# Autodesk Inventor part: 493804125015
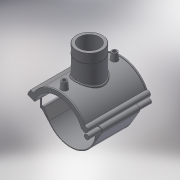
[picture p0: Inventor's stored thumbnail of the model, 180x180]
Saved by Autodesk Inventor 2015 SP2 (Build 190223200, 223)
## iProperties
Created: 2017-07
Part Number: 493804125015
Material: Generic
Description: PLASSON TRANSITION SADDLE 125-1.1/2"
Document SubType Name: Modeling
Designer: KIM
Density: 1 g/cm^3
Appearance: Default
Author: KIM
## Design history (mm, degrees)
derived "493804.ipt"
feature "Solid1::493804.ipt"
tag "TaggingFeature1"
body "Solid1"
other parameters: "d_" = 125, "B_" = 158, "H_" = 53, "L_" = 118, "d_t" = 6, "G_" = 44.845, "d148" = 1.875, "d160" = 1.875, "d169" = 2.1, "d192" = 4.2, "d0" = 125, "d1" = 145, "d2" = 158, "d3" = 31.25, "d4" = 118, "d5" = 0, "d6" = 0.1, "d8" = 0, "d19" = 6, "d20" = 6, "d21" = 70.8, "d23" = 0, "d24" = 35.4, "d26" = 0, "d27" = 3, "d28" = 3, "d29" = 3, "d30" = 41.66667, "d31" = 6, "d32" = 0, "d33" = 0, "d34" = 0.6, "d40" = 75.4, "d41" = 62.783, "d43" = 0, "d45" = 0, "d47" = 125.5, "d48" = 58.2985, "d50" = 0, "d70" = 15, "d72" = 0, "d73" = 6, "d75" = 5, "d76" = 0, "d77" = 6.25, "d78" = 92.5, "d79" = 15, "d80" = 47.2, "d82" = 5 deg, "d84" = 4, "d85" = 14, "d86" = 0, "d87" = 3, "d88" = 0, "d89" = 1, "d90" = 1, "d91" = 94.4, "d92" = 0, "d93" = 0.5, "d94" = 65.78947, "d96" = 147.9, "d97" = 2.36, "d98" = 0, "d102" = 1.34535, "d103" = 44.845, "d104" = 31.8, "d105" = 0, "d106" = 35.876, "d108" = 0, "d109" = -17.66667, "d111" = 0.5, "d112" = 0.5, "d113" = 0, "d114" = 0.5, "d117" = 0.44845, "d120" = 140 deg, "d121" = 24.228, "d122" = 20 deg, "d124" = 87, "d126" = 0, "d143" = 128.75, "d145" = 15.38462, "d149" = 1.875, "d150" = 16.92308, "d153" = 118, "d154" = 0, "d156" = 72.5, "d157" = 160 deg, "d159" = 4, "d161" = 1.875, "d162" = 70.8, "d163" = 0, "d164" = 62.5, "d167" = 12.5, "d168" = 70.73171, "d170" = 2.1, "d172" = 0, "d173" = 1, "d175" = 62.5, "d176" = 20 deg, "d177" = 8.75, "d180" = 0, "d183" = 8, "d184" = 7, "d185" = 38.35, "d186" = 38.35, "d187" = 72.5, "d188" = 6, "d189" = 8.75, "d190" = 0, "d191" = 87, "d193" = 4.2, "d194" = 2.95, "d195" = 90 deg, "d197" = 0, "d199" = 0
